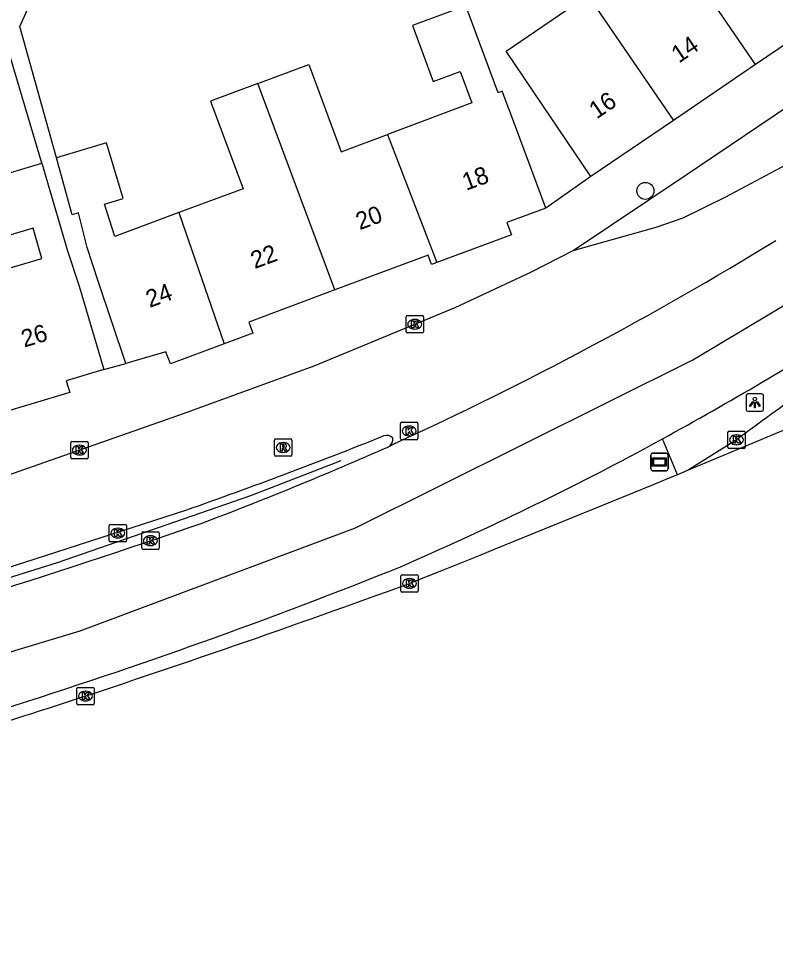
# Model space of a CAD drawing. Extents: x 161845 to 162341, y 381620 to 382158.
# Drawn here: x 162247.8 to 162291.3, y 381624.7 to 381677.4 of the extents above; entities that cross this region are included whole.
import ezdxf

# ---------------------------------------------------------------- set-up
doc = ezdxf.new("R2010")
doc.units = 0
for name, color, linetype in [('IMGEO_Berm_open', 7, 'Continuous'), ('IMGEO_Boom', 7, 'Continuous'), ('IMGEO_Fietspad_open', 7, 'Continuous'), ('IMGEO_Hek', 7, 'Continuous'), ('IMGEO_Kolk', 7, 'Continuous'), ('IMGEO_Lichtpunt', 7, 'Continuous'), ('IMGEO_Pand', 7, 'Continuous'), ('IMGEO_Pand_nummerreeks', 7, 'Continuous'), ('IMGEO_Reclamebord', 7, 'Continuous'), ('IMGEO_Rijbaan_lokaal_open', 7, 'Continuous'), ('IMGEO_Rijbaan_regionaal_gesloten', 7, 'Continuous'), ('IMGEO_Rioolput', 7, 'Continuous'), ('IMGEO_Voetpad_open', 7, 'Continuous')]:
    doc.layers.add(name, color=color, linetype=linetype)

msp = doc.modelspace()

# ---------------------------------------------------------------- linework, layer by layer
at = {"layer": 'IMGEO_Berm_open'}
msp.add_lwpolyline([(162285.668, 381651.131), (162284.808, 381653.192)], dxfattribs=at)
at = {"layer": 'IMGEO_Boom'}
msp.add_circle((162283.826, 381667.441), 0.489, dxfattribs=at)
at = {"layer": 'IMGEO_Fietspad_open'}
msp.add_lwpolyline([(162279.678, 381664.016), (162286.165, 381668.36), (162301.343, 381678.613), (162310.812, 381684.914)], dxfattribs=at)
at = {"layer": 'IMGEO_Hek'}
msp.add_lwpolyline([(162266.331, 381651.929), (162261.152, 381649.927), (162250.04, 381646.074), (162241.823, 381643.497), (162233.545, 381641.12), (162229.612, 381640.011), (162225.666, 381638.966), (162220.873, 381637.787), (162217.165, 381636.942), (162213.136, 381635.998), (162208.014, 381634.881), (162199.733, 381633.272), (162194.605, 381632.38), (162187.696, 381631.333), (162181.837, 381630.583), (162175.425, 381629.906), (162170.79, 381629.51), (162167.399, 381629.27), (162161.318, 381628.942), (162155.604, 381628.756), (162151.691, 381628.719), (162146.625, 381628.693)], dxfattribs=at)
at = {"layer": 'IMGEO_Kolk'}
for p, q in [((162270.079, 381659.352), (162270.079, 381660.204)), ((162270.154, 381660.278), (162271.006, 381660.278)), ((162270.567, 381660.058), (162270.592, 381660.058)), ((162271.08, 381660.204), (162271.08, 381659.352)), ((162270.59, 381659.498), (162270.565, 381659.498)), ((162271.006, 381659.278), (162270.154, 381659.278)), ((162269.762, 381653.22), (162269.762, 381654.072)), ((162269.837, 381654.146), (162270.689, 381654.146)), ((162270.25, 381653.926), (162270.275, 381653.926)), ((162270.763, 381654.072), (162270.763, 381653.22)), ((162288.636, 381653.638), (162289.488, 381653.638)), ((162270.689, 381653.146), (162269.837, 381653.146)), ((162270.273, 381653.366), (162270.248, 381653.366)), ((162288.561, 381652.712), (162288.561, 381653.564)), ((162289.049, 381653.418), (162289.074, 381653.418)), ((162289.562, 381653.564), (162289.562, 381652.712)), ((162250.817, 381652.12), (162250.817, 381652.972)), ((162250.892, 381653.046), (162251.744, 381653.046)), ((162251.305, 381652.826), (162251.33, 381652.826)), ((162251.818, 381652.972), (162251.818, 381652.12)), ((162289.488, 381652.638), (162288.636, 381652.638)), ((162289.072, 381652.858), (162289.047, 381652.858)), ((162251.328, 381652.266), (162251.303, 381652.266)), ((162251.744, 381652.046), (162250.892, 381652.046)), ((162253.022, 381647.354), (162253.022, 381648.206)), ((162253.097, 381648.28), (162253.949, 381648.28)), ((162253.51, 381648.06), (162253.535, 381648.06)), ((162254.023, 381648.206), (162254.023, 381647.354)), ((162254.97, 381647.844), (162255.822, 381647.844)), ((162253.533, 381647.5), (162253.508, 381647.5)), ((162254.895, 381646.918), (162254.895, 381647.77)), ((162255.383, 381647.624), (162255.408, 381647.624)), ((162255.896, 381647.77), (162255.896, 381646.918)), ((162253.949, 381647.28), (162253.097, 381647.28)), ((162255.822, 381646.844), (162254.97, 381646.844)), ((162255.406, 381647.064), (162255.381, 381647.064)), ((162269.779, 381644.462), (162269.779, 381645.314)), ((162269.854, 381645.388), (162270.706, 381645.388)), ((162270.78, 381645.314), (162270.78, 381644.462)), ((162270.267, 381645.168), (162270.292, 381645.168)), ((162270.706, 381644.388), (162269.854, 381644.388)), ((162270.29, 381644.608), (162270.265, 381644.608)), ((162251.241, 381638.913), (162252.093, 381638.913)), ((162251.166, 381637.987), (162251.166, 381638.839)), ((162251.654, 381638.693), (162251.679, 381638.693)), ((162252.167, 381638.839), (162252.167, 381637.987)), ((162252.093, 381637.913), (162251.241, 381637.913)), ((162251.677, 381638.133), (162251.652, 381638.133))]:
    msp.add_line(p, q, dxfattribs=at)
for points in [[(162270.079, 381659.352), (162270.079, 381660.204)], [(162270.154, 381660.278), (162271.006, 381660.278)], [(162270.4, 381659.978), (162270.523, 381659.978), (162270.523, 381659.827), (162270.653, 381659.978), (162270.817, 381659.978), (162270.671, 381659.827), (162270.824, 381659.578), (162270.672, 381659.578), (162270.587, 381659.742), (162270.523, 381659.675), (162270.523, 381659.578), (162270.4, 381659.578), (162270.4, 381659.978)], [(162271.08, 381660.204), (162271.08, 381659.352)], [(162271.006, 381659.278), (162270.154, 381659.278)], [(162269.762, 381653.22), (162269.762, 381654.072)], [(162269.837, 381654.146), (162270.689, 381654.146)], [(162270.083, 381653.846), (162270.206, 381653.846), (162270.206, 381653.695), (162270.336, 381653.846), (162270.5, 381653.846), (162270.354, 381653.695), (162270.507, 381653.446), (162270.355, 381653.446), (162270.27, 381653.61), (162270.206, 381653.543), (162270.206, 381653.446), (162270.083, 381653.446), (162270.083, 381653.846)], [(162270.763, 381654.072), (162270.763, 381653.22)], [(162288.636, 381653.638), (162289.488, 381653.638)], [(162270.689, 381653.146), (162269.837, 381653.146)], [(162288.561, 381652.712), (162288.561, 381653.564)], [(162288.882, 381653.338), (162289.005, 381653.338), (162289.005, 381653.187), (162289.135, 381653.338), (162289.299, 381653.338), (162289.153, 381653.187), (162289.306, 381652.938), (162289.154, 381652.938), (162289.069, 381653.102), (162289.005, 381653.035), (162289.005, 381652.938), (162288.882, 381652.938), (162288.882, 381653.338)], [(162289.562, 381653.564), (162289.562, 381652.712)], [(162250.817, 381652.12), (162250.817, 381652.972)], [(162250.892, 381653.046), (162251.744, 381653.046)], [(162251.138, 381652.746), (162251.261, 381652.746), (162251.261, 381652.595), (162251.391, 381652.746), (162251.555, 381652.746), (162251.409, 381652.595), (162251.562, 381652.346), (162251.41, 381652.346), (162251.325, 381652.51), (162251.261, 381652.443), (162251.261, 381652.346), (162251.138, 381652.346), (162251.138, 381652.746)], [(162251.818, 381652.972), (162251.818, 381652.12)], [(162289.488, 381652.638), (162288.636, 381652.638)], [(162251.744, 381652.046), (162250.892, 381652.046)], [(162253.022, 381647.354), (162253.022, 381648.206)], [(162253.097, 381648.28), (162253.949, 381648.28)], [(162253.343, 381647.98), (162253.466, 381647.98), (162253.466, 381647.829), (162253.596, 381647.98), (162253.76, 381647.98), (162253.614, 381647.829), (162253.767, 381647.58), (162253.615, 381647.58), (162253.53, 381647.744), (162253.466, 381647.677), (162253.466, 381647.58), (162253.343, 381647.58), (162253.343, 381647.98)], [(162254.023, 381648.206), (162254.023, 381647.354)], [(162254.97, 381647.844), (162255.822, 381647.844)], [(162254.895, 381646.918), (162254.895, 381647.77)], [(162255.216, 381647.544), (162255.339, 381647.544), (162255.339, 381647.393), (162255.469, 381647.544), (162255.633, 381647.544), (162255.487, 381647.393), (162255.64, 381647.144), (162255.488, 381647.144), (162255.403, 381647.308), (162255.339, 381647.241), (162255.339, 381647.144), (162255.216, 381647.144), (162255.216, 381647.544)], [(162255.896, 381647.77), (162255.896, 381646.918)], [(162253.949, 381647.28), (162253.097, 381647.28)], [(162255.822, 381646.844), (162254.97, 381646.844)], [(162269.779, 381644.462), (162269.779, 381645.314)], [(162269.854, 381645.388), (162270.706, 381645.388)], [(162270.78, 381645.314), (162270.78, 381644.462)], [(162270.1, 381645.088), (162270.223, 381645.088), (162270.223, 381644.937), (162270.353, 381645.088), (162270.517, 381645.088), (162270.371, 381644.937), (162270.524, 381644.688), (162270.372, 381644.688), (162270.287, 381644.852), (162270.223, 381644.785), (162270.223, 381644.688), (162270.1, 381644.688), (162270.1, 381645.088)], [(162270.706, 381644.388), (162269.854, 381644.388)], [(162251.241, 381638.913), (162252.093, 381638.913)], [(162251.166, 381637.987), (162251.166, 381638.839)], [(162251.487, 381638.613), (162251.61, 381638.613), (162251.61, 381638.462), (162251.74, 381638.613), (162251.904, 381638.613), (162251.758, 381638.462), (162251.911, 381638.213), (162251.759, 381638.213), (162251.674, 381638.377), (162251.61, 381638.31), (162251.61, 381638.213), (162251.487, 381638.213), (162251.487, 381638.613)], [(162252.167, 381638.839), (162252.167, 381637.987)], [(162252.093, 381637.913), (162251.241, 381637.913)]]:
    msp.add_lwpolyline(points, dxfattribs=at)
for centre, start, end in [((162270.156, 381660.202), 91.552, 178.448), ((162270.156, 381660.202), 91.552, 178.448), ((162271.004, 381660.202), 1.552, 88.448), ((162271.004, 381660.202), 1.552, 88.448), ((162270.156, 381659.354), 181.552, 268.448), ((162270.156, 381659.354), 181.552, 268.448), ((162271.004, 381659.354), 271.552, 358.448), ((162271.004, 381659.354), 271.552, 358.448), ((162269.839, 381654.07), 91.552, 178.448), ((162269.839, 381654.07), 91.552, 178.448), ((162270.687, 381654.07), 1.552, 88.448), ((162270.687, 381654.07), 1.552, 88.448), ((162288.638, 381653.562), 91.552, 178.448), ((162288.638, 381653.562), 91.552, 178.448), ((162289.486, 381653.562), 1.552, 88.448), ((162289.486, 381653.562), 1.552, 88.448), ((162269.839, 381653.222), 181.552, 268.448), ((162269.839, 381653.222), 181.552, 268.448), ((162270.687, 381653.222), 271.552, 358.448), ((162270.687, 381653.222), 271.552, 358.448), ((162250.894, 381652.97), 91.552, 178.448), ((162250.894, 381652.97), 91.552, 178.448), ((162251.742, 381652.97), 1.552, 88.448), ((162251.742, 381652.97), 1.552, 88.448), ((162288.638, 381652.714), 181.552, 268.448), ((162288.638, 381652.714), 181.552, 268.448), ((162289.486, 381652.714), 271.552, 358.448), ((162289.486, 381652.714), 271.552, 358.448), ((162250.894, 381652.122), 181.552, 268.448), ((162250.894, 381652.122), 181.552, 268.448), ((162251.742, 381652.122), 271.552, 358.448), ((162251.742, 381652.122), 271.552, 358.448), ((162253.099, 381648.204), 91.552, 178.448), ((162253.099, 381648.204), 91.552, 178.448), ((162253.947, 381648.204), 1.552, 88.448), ((162253.947, 381648.204), 1.552, 88.448), ((162254.972, 381647.768), 91.552, 178.448), ((162254.972, 381647.768), 91.552, 178.448), ((162255.82, 381647.768), 1.552, 88.448), ((162255.82, 381647.768), 1.552, 88.448), ((162253.099, 381647.356), 181.552, 268.448), ((162253.099, 381647.356), 181.552, 268.448), ((162253.947, 381647.356), 271.552, 358.448), ((162253.947, 381647.356), 271.552, 358.448), ((162254.972, 381646.92), 181.552, 268.448), ((162254.972, 381646.92), 181.552, 268.448), ((162255.82, 381646.92), 271.552, 358.448), ((162255.82, 381646.92), 271.552, 358.448), ((162269.856, 381645.312), 91.552, 178.448), ((162269.856, 381645.312), 91.552, 178.448), ((162270.704, 381645.312), 1.552, 88.448), ((162270.704, 381645.312), 1.552, 88.448), ((162269.856, 381644.464), 181.552, 268.448), ((162269.856, 381644.464), 181.552, 268.448), ((162270.704, 381644.464), 271.552, 358.448), ((162270.704, 381644.464), 271.552, 358.448), ((162251.243, 381638.837), 91.552, 178.448), ((162251.243, 381638.837), 91.552, 178.448), ((162252.091, 381638.837), 1.552, 88.448), ((162252.091, 381638.837), 1.552, 88.448), ((162251.243, 381637.989), 181.552, 268.448), ((162251.243, 381637.989), 181.552, 268.448), ((162252.091, 381637.989), 271.552, 358.448), ((162252.091, 381637.989), 271.552, 358.448)]:
    msp.add_arc(centre, 0.0765, start, end, dxfattribs=at)
for centre, major_axis, ratio, start_param, end_param in [((162270.566, 381659.778), (-0.387, 0.002), 0.722429, 4.712389, 7.853982), ((162270.591, 381659.778), (-0.39, 0.002), 0.717154, 1.570796, 4.712389), ((162270.249, 381653.646), (-0.387, 0.002), 0.722429, 4.712389, 7.853982), ((162270.274, 381653.646), (-0.39, 0.002), 0.717154, 1.570796, 4.712389), ((162289.048, 381653.138), (-0.387, 0.002), 0.722429, 4.712389, 7.853982), ((162289.073, 381653.138), (-0.39, 0.002), 0.717154, 1.570796, 4.712389), ((162251.304, 381652.546), (-0.387, 0.002), 0.722429, 4.712389, 7.853982), ((162251.329, 381652.546), (-0.39, 0.002), 0.717154, 1.570796, 4.712389), ((162253.509, 381647.78), (-0.387, 0.002), 0.722429, 4.712389, 7.853982), ((162253.534, 381647.78), (-0.39, 0.002), 0.717154, 1.570796, 4.712389), ((162255.382, 381647.344), (-0.387, 0.002), 0.722429, 4.712389, 7.853982), ((162255.407, 381647.344), (-0.39, 0.002), 0.717154, 1.570796, 4.712389), ((162270.266, 381644.888), (-0.387, 0.002), 0.722429, 4.712389, 7.853982), ((162270.291, 381644.888), (-0.39, 0.002), 0.717154, 1.570796, 4.712389), ((162251.653, 381638.413), (-0.387, 0.002), 0.722429, 4.712389, 7.853982), ((162251.678, 381638.413), (-0.39, 0.002), 0.717154, 1.570796, 4.712389)]:
    msp.add_ellipse(centre, major_axis=major_axis, ratio=ratio, start_param=start_param, end_param=end_param, dxfattribs=at)
at = {"layer": 'IMGEO_Lichtpunt'}
for p, q in [((162290.518, 381655.777), (162289.71, 381655.777)), ((162290.518, 381655.777), (162289.71, 381655.777)), ((162289.616, 381655.682), (162289.616, 381654.875)), ((162289.616, 381655.682), (162289.616, 381654.875)), ((162290.612, 381654.875), (162290.612, 381655.682)), ((162290.612, 381654.875), (162290.612, 381655.682)), ((162289.71, 381654.781), (162290.518, 381654.781)), ((162289.71, 381654.781), (162290.518, 381654.781))]:
    msp.add_line(p, q, dxfattribs=at)
for points in [[(162289.99, 381655.346), (162290.029, 381655.318), (162289.841, 381655.056), (162289.803, 381655.083), (162289.99, 381655.346)], [(162290.092, 381655.298), (162290.139, 381655.298), (162290.139, 381654.976), (162290.092, 381654.976), (162290.092, 381655.298)], [(162290.202, 381655.318), (162290.24, 381655.345), (162290.427, 381655.083), (162290.388, 381655.055), (162290.202, 381655.318)]]:
    msp.add_lwpolyline(points, dxfattribs=at)
msp.add_circle((162290.115, 381655.48), 0.0994, dxfattribs=at)
for centre, start, end in [((162289.71, 381655.682), 90, 180), ((162289.71, 381655.682), 90, 180), ((162290.518, 381655.682), 0, 90), ((162290.518, 381655.682), 0, 90), ((162289.71, 381654.875), 180, 270), ((162289.71, 381654.875), 180, 270), ((162290.518, 381654.875), 270, 0), ((162290.518, 381654.875), 270, 360)]:
    msp.add_arc(centre, 0.0946, start, end, dxfattribs=at)
at = {"layer": 'IMGEO_Pand'}
for points in [[(162290.158, 381674.701), (162285.24, 381681.899)], [(162280.693, 381668.267), (162277.891, 381672.408), (162275.822, 381675.465), (162280.531, 381678.682)], [(162280.531, 381678.682), (162285.441, 381671.495)], [(162278.109, 381666.451), (162276.362, 381671.136), (162275.604, 381673.17), (162275.377, 381673.085), (162273.513, 381678.083), (162273.143, 381677.945), (162270.442, 381676.938), (162271.638, 381673.733), (162273.183, 381674.309), (162273.861, 381672.492), (162269.014, 381670.685)], [(162294.874, 381677.907), (162290.158, 381674.701)], [(162261.572, 381673.615), (162264.493, 381674.704), (162266.36, 381669.695), (162269.014, 381670.685)], [(162290.158, 381674.701), (162285.441, 381671.495)], [(162261.572, 381673.615), (162258.849, 381672.6), (162260.726, 381667.567), (162257.036, 381666.192)], [(162265.997, 381661.75), (162261.572, 381673.615)], [(162285.441, 381671.495), (162280.693, 381668.267)], [(162269.014, 381670.685), (162271.849, 381663.328)], [(162257.036, 381666.192), (162253.346, 381664.817), (162252.76, 381666.678), (162253.831, 381666.997), (162252.881, 381670.197), (162250, 381669.341)], [(162244.469, 381662.169), (162249.169, 381663.565), (162248.656, 381665.291), (162247.19, 381664.855), (162246.21, 381668.154), (162249.155, 381669.029)], [(162249.155, 381669.029), (162250.64, 381664.006), (162251.298, 381661.967), (162252.722, 381657.173)], [(162253.991, 381657.521), (162252.402, 381662.262), (162251.757, 381664.185), (162251.257, 381666.176), (162250.909, 381666.073), (162250, 381669.341)], [(162278.109, 381666.451), (162275.876, 381665.618), (162276.134, 381664.925), (162271.849, 381663.328)], [(162257.036, 381666.192), (162259.64, 381658.653)], [(162271.849, 381663.328), (162271.544, 381663.214), (162271.347, 381663.744), (162265.997, 381661.75)], [(162265.997, 381661.75), (162261.052, 381659.906), (162261.289, 381659.268), (162259.64, 381658.653)], [(162259.64, 381658.653), (162256.541, 381657.498), (162256.279, 381658.2), (162253.991, 381657.521)], [(162252.722, 381657.173), (162250.565, 381656.532), (162250.766, 381655.856), (162246.647, 381654.632)]]:
    msp.add_lwpolyline(points, dxfattribs=at)
at = {"layer": 'IMGEO_Reclamebord'}
for p, q in [((162284.137, 381651.462), (162284.137, 381652.262)), ((162284.137, 381652.262), (162284.137, 381651.462)), ((162284.237, 381652.362), (162285.027, 381652.362)), ((162285.027, 381652.362), (162284.237, 381652.362)), ((162285.127, 381652.262), (162285.127, 381651.462)), ((162285.127, 381651.462), (162285.127, 381652.262)), ((162285.027, 381651.362), (162284.237, 381651.362)), ((162284.237, 381651.362), (162285.027, 381651.362))]:
    msp.add_line(p, q, dxfattribs=at)
for points in [[(162284.238, 381652.094), (162285.026, 381652.094), (162285.026, 381651.63), (162284.238, 381651.63), (162284.238, 381652.094)], [(162284.303, 381652.029), (162284.303, 381651.695), (162284.961, 381651.695), (162284.961, 381652.029), (162284.303, 381652.029)]]:
    msp.add_lwpolyline(points, dxfattribs=at)
for centre, start, end in [((162284.237, 381652.262), 90, 180), ((162284.237, 381652.262), 90, 180), ((162285.027, 381652.262), 0, 90), ((162285.027, 381652.262), 360, 90), ((162284.237, 381651.462), 180, 270), ((162284.237, 381651.462), 180, 270), ((162285.027, 381651.462), 270, 0), ((162285.027, 381651.462), 270, 0)]:
    msp.add_arc(centre, 0.1, start, end, dxfattribs=at)
at = {"layer": 'IMGEO_Rijbaan_lokaal_open'}
for points in [[(162279.678, 381664.016), (162284.442, 381665.356), (162285.99, 381665.89), (162288.456, 381667.106), (162291.599, 381668.782), (162293.515, 381669.819)], [(162243.686, 381649.981), (162246.43, 381650.83), (162257.303, 381654.644), (162264.812, 381657.392), (162272.909, 381660.74), (162277.242, 381662.769), (162279.678, 381664.016)], [(162245.018, 381645.086), (162257.495, 381649.12)]]:
    msp.add_lwpolyline(points, dxfattribs=at)
for centre, radius, start, end in [((162165.62, 381910.802), 277.342, 289.34594, 291.83949), ((162268.96, 381652.871), 0.521, 45.3636, 108.6472), ((162268.803, 381653.189), 0.526, 302.3368, 5.8289)]:
    msp.add_arc(centre, radius, start, end, dxfattribs=at)
at = {"layer": 'IMGEO_Rijbaan_regionaal_gesloten'}
for points in [[(162065.762, 381627.224), (162074.598, 381626.568), (162101.225, 381625.613), (162133.688, 381624.885), (162151.965, 381624.703), (162167.196, 381625.249), (162193.384, 381627.978), (162217.254, 381632.709), (162234.44, 381637.075), (162251.353, 381642.169), (162267.176, 381648.082), (162286.544, 381657.725), (162299.911, 381665.73), (162311.76, 381673.667)], [(162317.06, 381664.492), (162303.708, 381658.672), (162286.289, 381651.389)], [(162283.341, 381652.393), (162284.808, 381653.192)], [(162289.063, 381653.137), (162286.289, 381651.389)], [(162269.466, 381652.949), (162269.084, 381652.744)], [(162285.668, 381651.131), (162285.236, 381650.952), (162284.182, 381650.517), (162275.135, 381646.831), (162274.214, 381646.457), (162272.214, 381645.649), (162270.276, 381644.887)], [(162286.289, 381651.389), (162285.668, 381651.131)]]:
    msp.add_lwpolyline(points, dxfattribs=at)
for centre, radius, start, end in [((162185.076, 381837.704), 203.116, 294.54946, 301.5356), ((162176.26, 381850.779), 225.44, 298.78294, 302.11446), ((162377.94, 381534.003), 148.634, 122.9468, 126.72389), ((162180.63, 381853.348), 219.24, 290.75418, 293.79443), ((162192.469, 381823.385), 193.639, 293.55458, 297.98811), ((162120.639, 382045.642), 420.486, 285.34665, 289.11306), ((162153.724, 381934.069), 310.706, 287.45256, 291.94714), ((162052.153, 382242.332), 636.017, 288.134322, 290.056761), ((162122.85, 382030.969), 413.151, 285.56323, 287.94028)]:
    msp.add_arc(centre, radius, start, end, dxfattribs=at)
at = {"layer": 'IMGEO_Rioolput'}
for p, q in [((162262.517, 381652.271), (162262.517, 381653.123)), ((162262.592, 381653.197), (162263.444, 381653.197)), ((162263.518, 381653.123), (162263.518, 381652.271)), ((162263.005, 381652.977), (162263.03, 381652.977)), ((162263.444, 381652.197), (162262.592, 381652.197)), ((162263.028, 381652.417), (162263.003, 381652.417))]:
    msp.add_line(p, q, dxfattribs=at)
for points in [[(162262.517, 381652.271), (162262.517, 381653.123)], [(162262.592, 381653.197), (162263.444, 381653.197)], [(162263.518, 381653.123), (162263.518, 381652.271)], [(162263.106, 381652.895), (162262.854, 381652.897), (162262.854, 381652.497)], [(162262.854, 381652.497), (162262.978, 381652.497), (162262.978, 381652.659), (162262.989, 381652.659)], [(162263.032, 381652.816), (162262.978, 381652.816), (162262.978, 381652.735)], [(162262.978, 381652.735), (162263.03, 381652.735)], [(162263.036, 381652.63), (162263.107, 381652.497), (162263.247, 381652.497), (162263.182, 381652.623)], [(162263.444, 381652.197), (162262.592, 381652.197)]]:
    msp.add_lwpolyline(points, dxfattribs=at)
for centre, radius, start, end in [((162262.594, 381653.121), 0.0765, 91.552, 178.448), ((162262.594, 381653.121), 0.0765, 91.552, 178.448), ((162263.442, 381653.121), 0.0765, 1.552, 88.448), ((162263.442, 381653.121), 0.0765, 1.552, 88.448), ((162262.988, 381652.606), 0.0533, 26.0293, 88.6989), ((162263.014, 381652.924), 0.19, 274.7715, 282.9687), ((162263.038, 381652.72), 0.0964, 77.0061, 93.1865), ((162263.052, 381652.777), 0.0378, 276.6634, 79.6772), ((162263.105, 381652.785), 0.109, 350.3612, 89.416), ((162263.103, 381652.785), 0.112, 277.5842, 350.9817), ((162263.087, 381652.57), 0.108, 29.5134, 73.7905), ((162262.594, 381652.273), 0.0765, 181.552, 268.448), ((162262.594, 381652.273), 0.0765, 181.552, 268.448), ((162263.442, 381652.273), 0.0765, 271.552, 358.448), ((162263.442, 381652.273), 0.0765, 271.552, 358.448)]:
    msp.add_arc(centre, radius, start, end, dxfattribs=at)
for centre, major_axis, ratio, start_param, end_param in [((162263.004, 381652.697), (-0.387, 0.002), 0.722429, 4.712389, 7.853982), ((162263.029, 381652.697), (-0.39, 0.002), 0.717154, 1.570796, 4.712389)]:
    msp.add_ellipse(centre, major_axis=major_axis, ratio=ratio, start_param=start_param, end_param=end_param, dxfattribs=at)
at = {"layer": 'IMGEO_Voetpad_open'}
for points in [[(162250, 381669.341), (162247.899, 381676.893), (162251.815, 381685.625), (162257.658, 381698.653), (162261.095, 381706.338)], [(162249.155, 381669.029), (162247.052, 381676.144), (162238.757, 381673.589)], [(162280.693, 381668.267), (162278.109, 381666.451)], [(162252.722, 381657.173), (162253.991, 381657.521)]]:
    msp.add_lwpolyline(points, dxfattribs=at)

# ---------------------------------------------------------------- texts
at = {"layer": 'IMGEO_Pand_nummerreeks'}
for s, rotation, p in [('14', 34.2064, (162285.754, 381674.754)), ('16', 34.2064, (162281.031, 381671.543)), ('18', 20.3177, (162273.532, 381667.443)), ('20', 20.3177, (162267.418, 381665.18)), ('22', 20.3171, (162261.382, 381662.945)), ('24', 20.3177, (162255.356, 381660.714)), ('26', 16.6737, (162248.147, 381658.433))]:
    msp.add_text(s, height=1, rotation=rotation, dxfattribs=at).set_placement(p)

doc.saveas('drawing.dxf')
